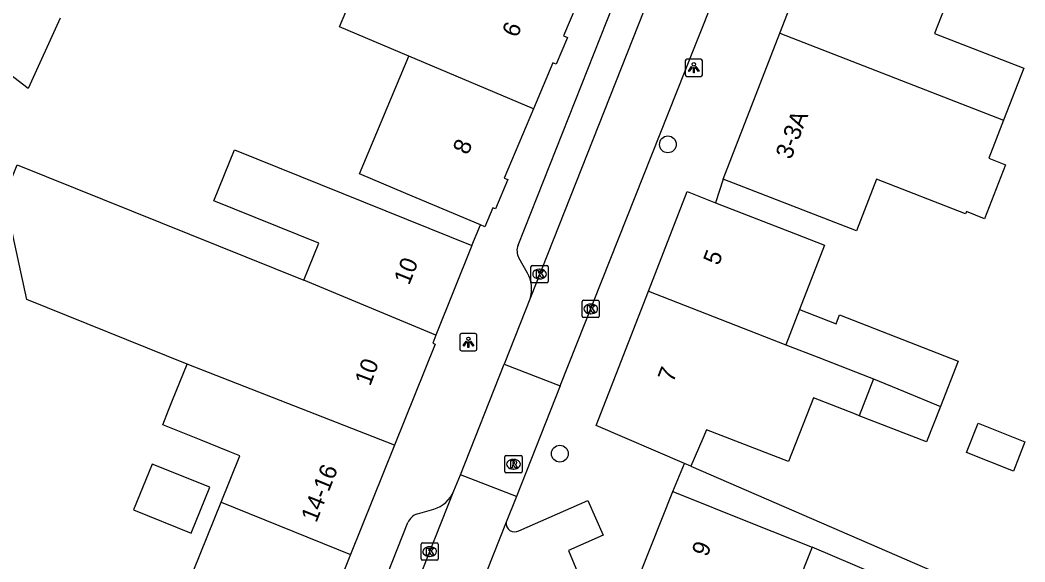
# Model space of a CAD drawing. Extents: x 161801 to 162379, y 382315 to 382832.
# Drawn here: x 162153.3 to 162211.8, y 382570.8 to 382602.3 of the extents above; entities that cross this region are included whole.
import ezdxf

# ---------------------------------------------------------------- set-up
doc = ezdxf.new("R2010")
doc.units = 0
for name, color, linetype in [('IMGEO_Boom', 7, 'Continuous'), ('IMGEO_Kolk', 7, 'Continuous'), ('IMGEO_Lichtpunt', 7, 'Continuous'), ('IMGEO_Pand', 7, 'Continuous'), ('IMGEO_Pand_nummerreeks', 7, 'Continuous'), ('IMGEO_Pand_vergunning_verleend', 7, 'Continuous'), ('IMGEO_Rijbaan_lokaal_open', 7, 'Continuous'), ('IMGEO_Rioolput', 7, 'Continuous'), ('IMGEO_Voetpad_open', 7, 'Continuous')]:
    doc.layers.add(name, color=color, linetype=linetype)

msp = doc.modelspace()

# ---------------------------------------------------------------- linework, layer by layer
at = {"layer": 'IMGEO_Boom'}
for centre in [(162191.042, 382595.118), (162184.752, 382577.129)]:
    msp.add_circle(centre, 0.489, dxfattribs=at)
at = {"layer": 'IMGEO_Kolk'}
for p, q in [((162183.072, 382587.148), (162183.072, 382588)), ((162183.147, 382588.074), (162183.999, 382588.074)), ((162184.073, 382588), (162184.073, 382587.148)), ((162183.56, 382587.854), (162183.585, 382587.854)), ((162183.999, 382587.074), (162183.147, 382587.074)), ((162183.583, 382587.294), (162183.558, 382587.294)), ((162186.048, 382585.122), (162186.048, 382585.974)), ((162186.123, 382586.048), (162186.975, 382586.048)), ((162186.536, 382585.828), (162186.561, 382585.828)), ((162187.049, 382585.974), (162187.049, 382585.122)), ((162186.975, 382585.048), (162186.123, 382585.048)), ((162186.559, 382585.268), (162186.534, 382585.268)), ((162176.674, 382571.008), (162176.674, 382571.86)), ((162176.749, 382571.934), (162177.601, 382571.934)), ((162177.162, 382571.714), (162177.187, 382571.714)), ((162177.675, 382571.86), (162177.675, 382571.008)), ((162177.185, 382571.154), (162177.16, 382571.154)), ((162177.601, 382570.934), (162176.749, 382570.934))]:
    msp.add_line(p, q, dxfattribs=at)
for points in [[(162183.072, 382587.148), (162183.072, 382588)], [(162183.147, 382588.074), (162183.999, 382588.074)], [(162184.073, 382588), (162184.073, 382587.148)], [(162183.393, 382587.774), (162183.516, 382587.774), (162183.516, 382587.623), (162183.646, 382587.774), (162183.81, 382587.774), (162183.664, 382587.623), (162183.817, 382587.374), (162183.665, 382587.374), (162183.58, 382587.538), (162183.516, 382587.471), (162183.516, 382587.374), (162183.393, 382587.374), (162183.393, 382587.774)], [(162183.999, 382587.074), (162183.147, 382587.074)], [(162186.048, 382585.122), (162186.048, 382585.974)], [(162186.123, 382586.048), (162186.975, 382586.048)], [(162186.369, 382585.748), (162186.492, 382585.748), (162186.492, 382585.597), (162186.622, 382585.748), (162186.786, 382585.748), (162186.64, 382585.597), (162186.793, 382585.348), (162186.641, 382585.348), (162186.556, 382585.512), (162186.492, 382585.445), (162186.492, 382585.348), (162186.369, 382585.348), (162186.369, 382585.748)], [(162187.049, 382585.974), (162187.049, 382585.122)], [(162186.975, 382585.048), (162186.123, 382585.048)], [(162176.674, 382571.008), (162176.674, 382571.86)], [(162176.749, 382571.934), (162177.601, 382571.934)], [(162176.995, 382571.634), (162177.118, 382571.634), (162177.118, 382571.483), (162177.248, 382571.634), (162177.412, 382571.634), (162177.266, 382571.483), (162177.419, 382571.234), (162177.267, 382571.234), (162177.182, 382571.398), (162177.118, 382571.331), (162177.118, 382571.234), (162176.995, 382571.234), (162176.995, 382571.634)], [(162177.675, 382571.86), (162177.675, 382571.008)], [(162177.601, 382570.934), (162176.749, 382570.934)]]:
    msp.add_lwpolyline(points, dxfattribs=at)
for centre, start, end in [((162183.149, 382587.998), 91.55205, 178.44795), ((162183.149, 382587.998), 91.55205, 178.44795), ((162183.997, 382587.998), 1.55205, 88.44795), ((162183.997, 382587.998), 1.55205, 88.44795), ((162183.149, 382587.15), 181.55205, 268.44795), ((162183.149, 382587.15), 181.55205, 268.44795), ((162183.997, 382587.15), 271.55205, 358.44795), ((162183.997, 382587.15), 271.55205, 358.44795), ((162186.125, 382585.972), 91.55205, 178.44795), ((162186.125, 382585.972), 91.55205, 178.44795), ((162186.973, 382585.972), 1.55205, 88.44795), ((162186.973, 382585.972), 1.55205, 88.44795), ((162186.125, 382585.124), 181.55205, 268.44795), ((162186.125, 382585.124), 181.55205, 268.44795), ((162186.973, 382585.124), 271.55205, 358.44795), ((162186.973, 382585.124), 271.55205, 358.44795), ((162176.751, 382571.858), 91.55205, 178.44795), ((162176.751, 382571.858), 91.55205, 178.44795), ((162177.599, 382571.858), 1.55205, 88.44795), ((162177.599, 382571.858), 1.55205, 88.44795), ((162176.751, 382571.01), 181.55205, 268.44795), ((162176.751, 382571.01), 181.55205, 268.44795), ((162177.599, 382571.01), 271.55205, 358.44795), ((162177.599, 382571.01), 271.55205, 358.44795)]:
    msp.add_arc(centre, 0.0765, start, end, dxfattribs=at)
for centre, major_axis, ratio, start_param, end_param in [((162183.559, 382587.574), (-0.387, 0.002), 0.722429, 4.712389, 7.853982), ((162183.584, 382587.574), (-0.39, 0.002), 0.717154, 1.570796, 4.712389), ((162186.535, 382585.548), (-0.387, 0.002), 0.722429, 4.712389, 7.853982), ((162186.56, 382585.548), (-0.39, 0.002), 0.717154, 1.570796, 4.712389), ((162177.161, 382571.434), (-0.387, 0.002), 0.722429, 4.712389, 7.853982), ((162177.186, 382571.434), (-0.39, 0.002), 0.717154, 1.570796, 4.712389)]:
    msp.add_ellipse(centre, major_axis=major_axis, ratio=ratio, start_param=start_param, end_param=end_param, dxfattribs=at)
at = {"layer": 'IMGEO_Lichtpunt'}
for p, q in [((162192.05, 382599.975), (162192.05, 382599.168)), ((162192.05, 382599.975), (162192.05, 382599.168)), ((162192.952, 382600.07), (162192.144, 382600.07)), ((162192.952, 382600.07), (162192.144, 382600.07)), ((162193.046, 382599.168), (162193.046, 382599.975)), ((162193.046, 382599.168), (162193.046, 382599.975)), ((162192.144, 382599.074), (162192.952, 382599.074)), ((162192.144, 382599.074), (162192.952, 382599.074)), ((162178.929, 382584.014), (162178.929, 382583.207)), ((162178.929, 382584.014), (162178.929, 382583.207)), ((162179.831, 382584.109), (162179.023, 382584.109)), ((162179.831, 382584.109), (162179.023, 382584.109)), ((162179.925, 382583.207), (162179.925, 382584.014)), ((162179.925, 382583.207), (162179.925, 382584.014)), ((162179.023, 382583.113), (162179.831, 382583.113)), ((162179.023, 382583.113), (162179.831, 382583.113))]:
    msp.add_line(p, q, dxfattribs=at)
for points in [[(162192.424, 382599.639), (162192.463, 382599.611), (162192.275, 382599.349), (162192.237, 382599.376), (162192.424, 382599.639)], [(162192.526, 382599.591), (162192.573, 382599.591), (162192.573, 382599.269), (162192.526, 382599.269), (162192.526, 382599.591)], [(162192.636, 382599.611), (162192.674, 382599.638), (162192.861, 382599.376), (162192.822, 382599.348), (162192.636, 382599.611)], [(162179.303, 382583.678), (162179.342, 382583.65), (162179.154, 382583.388), (162179.116, 382583.415), (162179.303, 382583.678)], [(162179.405, 382583.63), (162179.452, 382583.63), (162179.452, 382583.308), (162179.405, 382583.308), (162179.405, 382583.63)], [(162179.515, 382583.65), (162179.553, 382583.677), (162179.74, 382583.415), (162179.701, 382583.387), (162179.515, 382583.65)]]:
    msp.add_lwpolyline(points, dxfattribs=at)
for centre in [(162192.549, 382599.773), (162179.428, 382583.812)]:
    msp.add_circle(centre, 0.0994, dxfattribs=at)
for centre, start, end in [((162192.144, 382599.975), 90, 180), ((162192.144, 382599.975), 90, 180), ((162192.952, 382599.975), 0, 90), ((162192.952, 382599.975), 0, 90), ((162192.144, 382599.168), 180, 270), ((162192.144, 382599.168), 180, 270), ((162192.952, 382599.168), 270, 0), ((162192.952, 382599.168), 270, 360), ((162179.023, 382584.014), 90, 180), ((162179.023, 382584.014), 90, 180), ((162179.831, 382584.014), 0, 90), ((162179.831, 382584.014), 0, 90), ((162179.023, 382583.207), 180, 270), ((162179.023, 382583.207), 180, 270), ((162179.831, 382583.207), 270, 0), ((162179.831, 382583.207), 270, 360)]:
    msp.add_arc(centre, 0.0946, start, end, dxfattribs=at)
at = {"layer": 'IMGEO_Pand'}
for points in [[(162175.969, 382600.244), (162171.926, 382601.949), (162174.296, 382607.57), (162174.764, 382608.68)], [(162197.557, 382601.585), (162199.956, 382607.761)], [(162202.657, 382606.606), (162207.255, 382604.641), (162207.687, 382604.456), (162206.561, 382601.558), (162211.748, 382599.543), (162210.577, 382596.529)], [(162155.664, 382602.458), (162153.802, 382598.368), (162150.609, 382600.809), (162153.357, 382604.46)], [(162186.072, 382604.052), (162184.969, 382601.438), (162185.196, 382601.342), (162184.536, 382599.778), (162184.341, 382599.861), (162183.215, 382597.194)], [(162194.258, 382593.095), (162197.557, 382601.585)], [(162197.557, 382601.585), (162210.577, 382596.529)], [(162180.133, 382590.434), (162175.788, 382592.269), (162173.084, 382593.41), (162175.969, 382600.244)], [(162183.215, 382597.194), (162175.969, 382600.244)], [(162183.215, 382597.194), (162181.511, 382593.155), (162181.717, 382593.068), (162181.001, 382591.372), (162180.861, 382591.431), (162180.394, 382590.324), (162180.133, 382590.434)], [(162210.577, 382596.529), (162209.715, 382594.309), (162210.685, 382593.932), (162209.467, 382590.796), (162208.415, 382591.204), (162208.365, 382591.076), (162203.184, 382593.089), (162202.016, 382590.081), (162198.919, 382591.284), (162194.258, 382593.095)], [(162169.858, 382587.213), (162170.728, 382589.376), (162164.617, 382591.834), (162165.808, 382594.796), (162179.636, 382589.236)], [(162163.057, 382582.342), (162153.719, 382586.097), (162152.432, 382592.088), (162153.17, 382593.924), (162169.858, 382587.213)], [(162189.907, 382586.575), (162192.158, 382592.368), (162193.809, 382591.727)], [(162193.809, 382591.727), (162198.47, 382589.917), (162200.163, 382589.258), (162198.709, 382585.516)], [(162179.636, 382589.236), (162177.539, 382584.02)], [(162177.539, 382584.02), (162169.858, 382587.213)], [(162192.01, 382576.554), (162186.87, 382578.758), (162189.907, 382586.575)], [(162189.907, 382586.575), (162197.912, 382583.464)], [(162198.709, 382585.516), (162197.912, 382583.464)], [(162198.709, 382585.516), (162200.84, 382584.689), (162201.036, 382585.195), (162207.94, 382582.514), (162206.909, 382579.875)], [(162177.539, 382584.02), (162177.354, 382583.56), (162177.487, 382583.507), (162175.121, 382577.623)], [(162197.912, 382583.464), (162199.819, 382582.722), (162202.76, 382581.579), (162203.015, 382581.474)], [(162165.033, 382574.299), (162166.122, 382577.007), (162165.445, 382577.279), (162163.87, 382577.912), (162161.636, 382578.81), (162161.979, 382579.663), (162162.215, 382580.249), (162163.057, 382582.342)], [(162175.121, 382577.623), (162163.057, 382582.342)], [(162203.015, 382581.474), (162202.18, 382579.336)], [(162203.015, 382581.474), (162204.749, 382580.762), (162206.909, 382579.875)], [(162202.18, 382579.336), (162201.962, 382579.421), (162199.507, 382580.375), (162198.066, 382576.668), (162193.297, 382578.521), (162193.239, 382578.387), (162193.08, 382578.017), (162192.384, 382576.394)], [(162206.909, 382579.875), (162206.102, 382577.812), (162202.18, 382579.336)], [(162175.121, 382577.623), (162172.565, 382571.268)], [(162159.945, 382573.856), (162163.302, 382572.504), (162164.376, 382575.172), (162161.018, 382576.523), (162159.945, 382573.856)], [(162192.384, 382576.394), (162192.01, 382576.554)], [(162189.401, 382570.101), (162191.32, 382574.925)], [(162191.32, 382574.925), (162195.967, 382573.077), (162199.431, 382571.699)], [(162163.047, 382569.361), (162165.033, 382574.299)], [(162165.033, 382574.299), (162172.565, 382571.268)], [(162199.431, 382571.699), (162197.495, 382566.833)], [(162172.565, 382571.268), (162170.58, 382566.332)]]:
    msp.add_lwpolyline(points, dxfattribs=at)
at = {"layer": 'IMGEO_Pand_vergunning_verleend'}
msp.add_lwpolyline([(162208.422, 382577.199), (162209.095, 382578.894), (162211.82, 382577.812), (162211.147, 382576.117), (162208.422, 382577.199)], dxfattribs=at)
at = {"layer": 'IMGEO_Rijbaan_lokaal_open'}
for points in [[(162198.183, 382624.669), (162196.606, 382620.511), (162183.036, 382586.209)], [(162184.773, 382581.075), (162192.527, 382600.624), (162193.938, 382604.183), (162196.082, 382609.705), (162197.87, 382614.249)], [(162183.036, 382586.209), (162181.51, 382582.342)], [(162178.971, 382575.905), (162181.51, 382582.342)], [(162181.51, 382582.342), (162184.773, 382581.075)], [(162184.773, 382581.075), (162182.222, 382574.642)], [(162178.575, 382574.96), (162178.971, 382575.905)], [(162182.222, 382574.642), (162178.971, 382575.905)], [(162170.621, 382554.892), (162178.575, 382574.96)], [(162182.222, 382574.642), (162181.625, 382573.137)], [(162181.625, 382573.137), (162171.513, 382547.64)]]:
    msp.add_lwpolyline(points, dxfattribs=at)
at = {"layer": 'IMGEO_Rioolput'}
for p, q in [((162181.551, 382576.09), (162181.551, 382576.942)), ((162181.626, 382577.016), (162182.478, 382577.016)), ((162182.552, 382576.942), (162182.552, 382576.09)), ((162182.039, 382576.796), (162182.064, 382576.796)), ((162182.478, 382576.016), (162181.626, 382576.016)), ((162182.062, 382576.236), (162182.037, 382576.236))]:
    msp.add_line(p, q, dxfattribs=at)
for points in [[(162181.551, 382576.09), (162181.551, 382576.942)], [(162181.626, 382577.016), (162182.478, 382577.016)], [(162182.552, 382576.942), (162182.552, 382576.09)], [(162182.14, 382576.714), (162181.888, 382576.716), (162181.888, 382576.316)], [(162181.888, 382576.316), (162182.012, 382576.316), (162182.012, 382576.478), (162182.023, 382576.478)], [(162182.066, 382576.635), (162182.012, 382576.635), (162182.012, 382576.554)], [(162182.012, 382576.554), (162182.064, 382576.554)], [(162182.07, 382576.449), (162182.141, 382576.316), (162182.281, 382576.316), (162182.216, 382576.442)], [(162182.478, 382576.016), (162181.626, 382576.016)]]:
    msp.add_lwpolyline(points, dxfattribs=at)
for centre, radius, start, end in [((162181.628, 382576.94), 0.0765, 91.55205, 178.44795), ((162181.628, 382576.94), 0.0765, 91.55205, 178.44795), ((162182.476, 382576.94), 0.0765, 1.55205, 88.44795), ((162182.476, 382576.94), 0.0765, 1.55205, 88.44795), ((162182.022, 382576.425), 0.0533, 26.02933, 88.69889), ((162182.048, 382576.743), 0.19, 274.7715, 282.96867), ((162182.072, 382576.539), 0.0964, 77.00612, 93.18647), ((162182.086, 382576.596), 0.0378, 276.66336, 79.67722), ((162182.139, 382576.604), 0.109, 350.36119, 89.41601), ((162182.137, 382576.604), 0.112, 277.58423, 350.98172), ((162182.121, 382576.389), 0.108, 29.51342, 73.79051), ((162181.628, 382576.092), 0.0765, 181.55205, 268.44795), ((162181.628, 382576.092), 0.0765, 181.55205, 268.44795), ((162182.476, 382576.092), 0.0765, 271.55205, 358.44795), ((162182.476, 382576.092), 0.0765, 271.55205, 358.44795)]:
    msp.add_arc(centre, radius, start, end, dxfattribs=at)
for centre, major_axis, ratio, start_param, end_param in [((162182.038, 382576.516), (-0.387, 0.002), 0.722429, 4.712389, 7.853982), ((162182.063, 382576.516), (-0.39, 0.002), 0.717154, 1.570796, 4.712389)]:
    msp.add_ellipse(centre, major_axis=major_axis, ratio=ratio, start_param=start_param, end_param=end_param, dxfattribs=at)
at = {"layer": 'IMGEO_Voetpad_open'}
for points in [[(162182.318, 382589.26), (162190.44, 382609.748), (162191.828, 382613.249), (162194.908, 382621.019), (162195.498, 382622.698)], [(162194.258, 382593.095), (162193.809, 382591.727)], [(162179.636, 382589.236), (162180.133, 382590.434)], [(162182.871, 382587.63), (162182.369, 382588.517)], [(162191.32, 382574.925), (162192.01, 382576.554)], [(162192.384, 382576.394), (162209.772, 382568.862), (162210.278, 382567.499)], [(162182.369, 382572.638), (162186.384, 382574.415), (162187.28, 382572.39), (162185.253, 382571.505), (162186.115, 382569.439), (162184.061, 382568.472), (162184.969, 382566.473), (162182.929, 382565.575), (162183.78, 382563.584), (162181.758, 382562.683), (162182.642, 382560.634), (162180.621, 382559.742), (162181.471, 382557.698), (162179.444, 382556.811), (162180.323, 382554.783), (162178.3, 382553.854), (162179.247, 382551.849), (162172.902, 382548.953)], [(162176.46, 382573.621), (162177.412, 382573.901)], [(162169.897, 382557.907), (162175.91, 382573.119)], [(162208.629, 382567.001), (162207.999, 382568.054), (162199.431, 382571.699)]]:
    msp.add_lwpolyline(points, dxfattribs=at)
for centre, radius, start, end in [((162183.118, 382588.942), 0.861, 158.30413, 209.54919), ((162181.266, 382586.724), 1.843, 343.78925, 29.45727), ((162176.891, 382575.641), 1.816, 286.66195, 337.97854), ((162176.702, 382572.804), 0.852, 106.48277, 158.29234), ((162182.137, 382573.097), 0.514, 175.5095, 296.79107)]:
    msp.add_arc(centre, radius, start, end, dxfattribs=at)

# ---------------------------------------------------------------- texts
at = {"layer": 'IMGEO_Pand_nummerreeks'}
for s, rotation, p in [('6', 67.17961, (162182.269, 382601.279)), ('3-3A', 68.76797, (162198.203, 382594.192)), ('8', 67.17961, (162179.401, 382594.461)), ('5', 68.76639, (162193.99, 382588.027)), ('10', 68.09828, (162175.977, 382586.889)), ('10', 69.29393, (162173.712, 382581.022)), ('7', 68.76639, (162191.346, 382581.222)), ('14-16', 68.09603, (162170.575, 382573.072)), ('9', 68.30752, (162193.321, 382571.081))]:
    msp.add_text(s, height=1, rotation=rotation, dxfattribs=at).set_placement(p)

doc.saveas('drawing.dxf')
